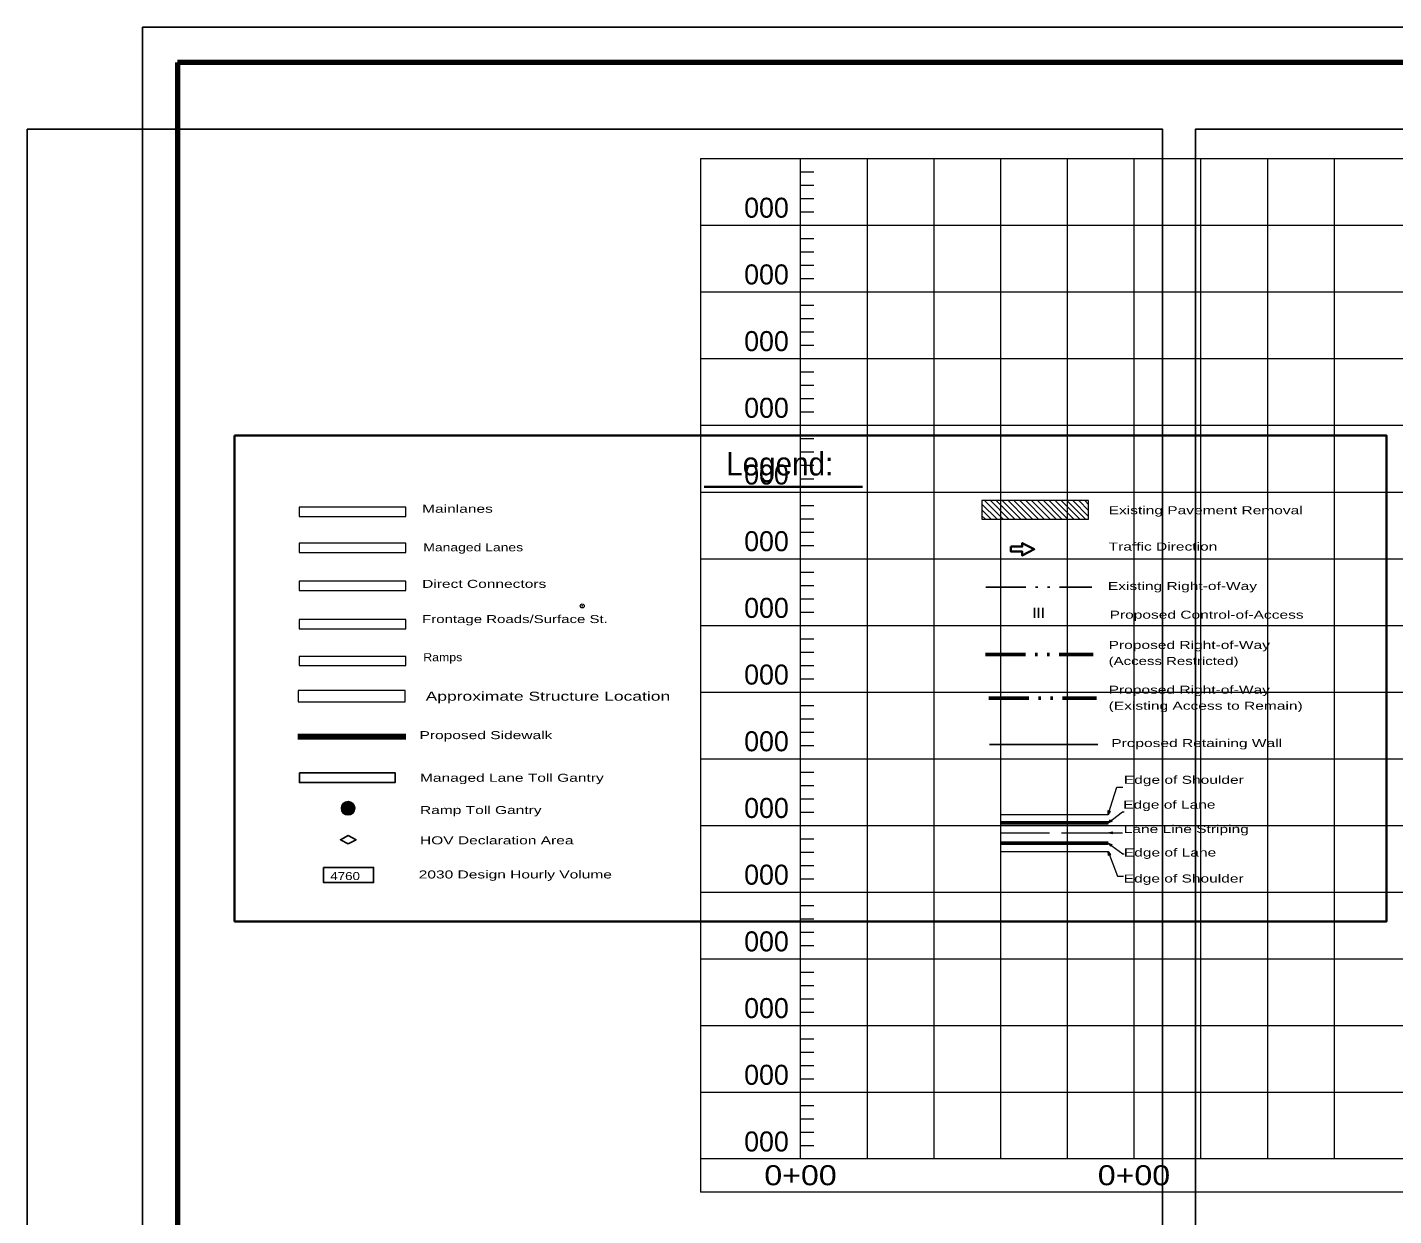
# Model space of a CAD drawing. Extents: x 2246932 to 2264252, y 7095151 to 7098651.
# Drawn here: x 2246932 to 2248981, y 7096869 to 7098651 of the extents above; entities that cross this region are included whole.
import ezdxf
from ezdxf.enums import TextEntityAlignment as Align

# ---------------------------------------------------------------- set-up
doc = ezdxf.new("R2010")
doc.units = 0
doc.header["$LTSCALE"] = 12
doc.header["$PDMODE"] = 32
doc.header["$PDSIZE"] = 6
doc.linetypes.add('DASH_DOUBLE_DOT', pattern=[9.2, 5, -1.2, 0.3, -1.2, 0.3, -1.2])
doc.linetypes.add('LONG_DASHED', pattern=[7.5, 6, -1.5])
for name, color, linetype, lineweight in [('1', 7, 'Continuous', 80), ('21', 7, 'Continuous', 13), ('62', 7, 'Continuous', 13), ('63', 7, 'Continuous', 25)]:
    doc.layers.add(name, color=color, linetype=linetype, lineweight=lineweight)
doc.layers.add('22', color=7, linetype='Continuous')

msp = doc.modelspace()

# ---------------------------------------------------------------- hatches: boundary and pattern name
at = {"layer": '21'}
for points in [[(2247422.99, 7097479.89, 1), (2247403.01, 7097479.89, 1)], [(2248555.86, 7097475.64), (2248552.59, 7097470.39), (2248553.01, 7097476.56)], [(2248558.25, 7097460.37), (2248552.59, 7097457.89), (2248556.42, 7097462.74)], [(2248558.62, 7097441.5), (2248552.59, 7097442.89), (2248558.56, 7097444.5)], [(2248556.52, 7097423.12), (2248552.59, 7097427.89), (2248558.31, 7097425.53)], [(2248553.33, 7097409.25), (2248552.59, 7097415.39), (2248556.14, 7097410.32)]]:
    msp.add_hatch(color=256, dxfattribs=at).paths.add_polyline_path(points)

# ---------------------------------------------------------------- linework, layer by layer
at = {"layer": '1'}
for p, q in [((2247157.08, 7098598.35), (2247157.09, 7095203.35)), ((2264052.09, 7098598.35), (2247157.09, 7098598.35))]:
    msp.add_line(p, q, dxfattribs=at)
at = {"layer": '1', "lineweight": 25}
msp.add_lwpolyline([(2264104.59, 7095150.85), (2264104.59, 7098650.85), (2247104.59, 7098650.85), (2247104.59, 7095150.85)], dxfattribs=at)
at = {"layer": '21', "lineweight": 35}
msp.add_line((2247947.17, 7097961.8), (2248184.63, 7097961.8), dxfattribs=at)
at = {"layer": '21'}
for p, q in [((2248386.29, 7097913.34), (2248363.52, 7097936.11)), ((2248395.13, 7097913.34), (2248367.3, 7097941.18)), ((2248403.97, 7097913.34), (2248376.14, 7097941.18)), ((2248412.81, 7097913.34), (2248384.98, 7097941.18)), ((2248421.65, 7097913.34), (2248393.81, 7097941.18)), ((2248430.49, 7097913.34), (2248402.65, 7097941.18)), ((2248439.33, 7097913.34), (2248411.49, 7097941.18)), ((2248448.17, 7097913.34), (2248420.33, 7097941.18)), ((2248457.01, 7097913.34), (2248429.17, 7097941.18)), ((2248465.84, 7097913.34), (2248438.01, 7097941.18)), ((2248474.68, 7097913.34), (2248446.85, 7097941.18)), ((2248483.52, 7097913.34), (2248455.69, 7097941.18)), ((2248492.36, 7097913.34), (2248464.52, 7097941.18)), ((2248501.2, 7097913.34), (2248473.36, 7097941.18)), ((2248510.04, 7097913.34), (2248482.2, 7097941.18)), ((2248518.88, 7097913.34), (2248491.04, 7097941.18)), ((2248523.53, 7097917.53), (2248499.88, 7097941.18)), ((2248523.53, 7097926.36), (2248508.72, 7097941.18)), ((2248523.53, 7097935.2), (2248517.56, 7097941.18)), ((2248377.46, 7097913.34), (2248363.52, 7097927.27)), ((2248368.62, 7097913.34), (2248363.52, 7097918.43)), ((2248552.59, 7097470.39), (2248565.97, 7097511.8)), ((2248565.97, 7097511.8), (2248574.73, 7097511.8)), ((2248392.58, 7097470.39), (2248552.59, 7097470.39)), ((2248552.59, 7097457.89), (2248574.48, 7097474.79)), ((2248574.48, 7097474.79), (2248576.75, 7097474.79)), ((2248552.59, 7097442.89), (2248574.48, 7097443.31)), ((2248552.59, 7097427.89), (2248574.91, 7097411.41)), ((2248392.58, 7097415.39), (2248552.59, 7097415.39)), ((2248552.59, 7097415.39), (2248566.82, 7097378.23)), ((2248574.91, 7097411.41), (2248577, 7097411.41)), ((2248566.82, 7097378.23), (2248575.74, 7097378.23))]:
    msp.add_line(p, q, dxfattribs=at)
at = {"layer": '21', "linetype": 'DASH_DOUBLE_DOT', "lineweight": 25}
msp.add_line((2248369.4, 7097811.29), (2248528.43, 7097811.29), dxfattribs=at)
at = {"layer": '21', "lineweight": 25}
for p, q in [((2248442.16, 7097780.54), (2248442.16, 7097765.54)), ((2248448.41, 7097780.54), (2248448.41, 7097765.54)), ((2248454.66, 7097780.54), (2248454.66, 7097765.54)), ((2248375.07, 7097575.48), (2248537.1, 7097575.48))]:
    msp.add_line(p, q, dxfattribs=at)
at = {"layer": '21', "linetype": 'DASH_DOUBLE_DOT', "lineweight": 53}
for p, q in [((2248368.86, 7097710.68), (2248530.41, 7097710.68)), ((2248373.74, 7097645.27), (2248535.3, 7097645.27))]:
    msp.add_line(p, q, dxfattribs=at)
at = {"layer": '21', "lineweight": 106}
msp.add_line((2247337.89, 7097587.33), (2247499.92, 7097587.33), dxfattribs=at)
at = {"layer": '21', "lineweight": 53}
for p, q in [((2248392.58, 7097457.89), (2248552.59, 7097457.89)), ((2248392.58, 7097427.89), (2248552.59, 7097427.89))]:
    msp.add_line(p, q, dxfattribs=at)
at = {"layer": '21', "linetype": 'LONG_DASHED'}
msp.add_line((2248392.58, 7097442.89), (2248552.59, 7097442.89), dxfattribs=at)
at = {"layer": '21', "lineweight": 35}
for points in [[(2247242.96, 7098038.69), (2248970.28, 7098038.69), (2248970.28, 7097310.27), (2247242.96, 7097310.27)], [(2248407.04, 7097872.4), (2248407.03, 7097864.89), (2248424.05, 7097864.87), (2248424.04, 7097858.78), (2248442.06, 7097868.21), (2248424.06, 7097877.67), (2248424.06, 7097872.38)]]:
    msp.add_lwpolyline(points, close=True, dxfattribs=at)
at = {"layer": '21'}
for points in [[(2247339.66, 7097917.61), (2247499.71, 7097917.61), (2247499.71, 7097931.45), (2247339.66, 7097931.45)], [(2248363.52, 7097913.34), (2248523.53, 7097913.34), (2248523.53, 7097941.18), (2248363.52, 7097941.18)], [(2247339.66, 7097863.38), (2247499.71, 7097863.38), (2247499.71, 7097877.22), (2247339.66, 7097877.22)], [(2247339.66, 7097806.7), (2247499.71, 7097806.7), (2247499.71, 7097820.54), (2247339.66, 7097820.54)], [(2247339.66, 7097749.07), (2247499.71, 7097749.07), (2247499.71, 7097762.91), (2247339.66, 7097762.91)], [(2247339.66, 7097693.79), (2247499.71, 7097693.79), (2247499.71, 7097707.62), (2247339.66, 7097707.62)], [(2247338.12, 7097639.59), (2247498.52, 7097639.57), (2247498.52, 7097656.53), (2247338.12, 7097656.56)], [(2248555.86, 7097475.64), (2248552.59, 7097470.39), (2248553.01, 7097476.56)], [(2248558.25, 7097460.37), (2248552.59, 7097457.89), (2248556.42, 7097462.74)], [(2248558.62, 7097441.5), (2248552.59, 7097442.89), (2248558.56, 7097444.5)], [(2248556.52, 7097423.12), (2248552.59, 7097427.89), (2248558.31, 7097425.53)], [(2248553.33, 7097409.25), (2248552.59, 7097415.39), (2248556.14, 7097410.32)]]:
    msp.add_lwpolyline(points, close=True, dxfattribs=at)
at = {"layer": '21', "lineweight": 25}
for points in [[(2247340.2, 7097533.25), (2247483.52, 7097533.25), (2247483.52, 7097518.52), (2247340.2, 7097518.52)], [(2247413.4, 7097426.51), (2247425.11, 7097432.82), (2247413.4, 7097439.13), (2247401.68, 7097432.82)], [(2247376.38, 7097391.28), (2247451.24, 7097391.28), (2247451.24, 7097368.62), (2247376.38, 7097368.62)]]:
    msp.add_lwpolyline(points, close=True, dxfattribs=at)
msp.add_circle((2247413, 7097479.89), 9.99, dxfattribs=at)
at = {"layer": '21'}
msp.add_point((2247764.18, 7097783.24), dxfattribs=at)
at = {"layer": '62'}
for p, q in [((2247941.45, 7098454.14), (2247941.45, 7096904.14)), ((2247941.45, 7098454.14), (2263241.45, 7098454.14)), ((2248091.45, 7096954.14), (2248091.45, 7098454.14)), ((2248191.45, 7098454.14), (2248191.45, 7096954.14)), ((2248291.45, 7098454.14), (2248291.45, 7096954.14)), ((2248391.45, 7098454.14), (2248391.45, 7096954.14)), ((2248491.45, 7098454.14), (2248491.45, 7096954.14)), ((2248591.45, 7098454.14), (2248591.45, 7096954.14)), ((2248691.45, 7098454.14), (2248691.45, 7096954.14)), ((2248791.45, 7098454.14), (2248791.45, 7096954.14)), ((2248891.45, 7098454.14), (2248891.45, 7096954.14)), ((2248091.45, 7098434.14), (2248111.45, 7098434.14)), ((2248091.45, 7098414.14), (2248111.45, 7098414.14)), ((2248091.45, 7098394.14), (2248111.45, 7098394.14)), ((2248091.45, 7098374.14), (2248111.45, 7098374.14)), ((2247941.45, 7098354.14), (2248091.45, 7098354.14)), ((2248091.45, 7098334.14), (2248111.45, 7098334.14)), ((2248091.45, 7098314.14), (2248111.45, 7098314.14)), ((2248091.45, 7098294.14), (2248111.45, 7098294.14)), ((2248091.45, 7098274.14), (2248111.45, 7098274.14)), ((2247941.45, 7098254.14), (2248091.45, 7098254.14)), ((2248091.45, 7098234.14), (2248111.45, 7098234.14)), ((2248091.45, 7098214.14), (2248111.45, 7098214.14)), ((2248091.45, 7098194.14), (2248111.45, 7098194.14)), ((2248091.45, 7098174.14), (2248111.45, 7098174.14)), ((2247941.45, 7098154.14), (2248091.45, 7098154.14)), ((2248091.45, 7098134.14), (2248111.45, 7098134.14)), ((2248091.45, 7098114.14), (2248111.45, 7098114.14)), ((2248091.45, 7098094.14), (2248111.45, 7098094.14)), ((2248091.45, 7098074.14), (2248111.45, 7098074.14)), ((2247941.45, 7098054.14), (2248091.45, 7098054.14)), ((2248091.45, 7098034.14), (2248111.45, 7098034.14)), ((2248091.45, 7098014.14), (2248111.45, 7098014.14)), ((2248091.45, 7097994.14), (2248111.45, 7097994.14)), ((2248091.45, 7097974.14), (2248111.45, 7097974.14)), ((2247941.45, 7097954.14), (2248091.45, 7097954.14)), ((2248091.45, 7097934.14), (2248111.45, 7097934.14)), ((2248091.45, 7097914.14), (2248111.45, 7097914.14)), ((2248091.45, 7097894.14), (2248111.45, 7097894.14)), ((2248091.45, 7097874.14), (2248111.45, 7097874.14)), ((2247941.45, 7097854.14), (2248091.45, 7097854.14)), ((2248091.45, 7097834.14), (2248111.45, 7097834.14)), ((2248091.45, 7097814.14), (2248111.45, 7097814.14)), ((2248091.45, 7097794.14), (2248111.45, 7097794.14)), ((2248091.45, 7097774.14), (2248111.45, 7097774.14)), ((2247941.45, 7097754.14), (2248091.45, 7097754.14)), ((2248091.45, 7097734.14), (2248111.45, 7097734.14)), ((2248091.45, 7097714.14), (2248111.45, 7097714.14)), ((2248091.45, 7097694.14), (2248111.45, 7097694.14)), ((2248091.45, 7097674.14), (2248111.45, 7097674.14)), ((2247941.45, 7097654.14), (2248091.45, 7097654.14)), ((2248091.45, 7097634.14), (2248111.45, 7097634.14)), ((2248091.45, 7097614.14), (2248111.45, 7097614.14)), ((2248091.45, 7097594.14), (2248111.45, 7097594.14)), ((2248091.45, 7097574.14), (2248111.45, 7097574.14)), ((2247941.45, 7097554.14), (2248091.45, 7097554.14)), ((2248091.45, 7097534.14), (2248111.45, 7097534.14)), ((2248091.45, 7097514.14), (2248111.45, 7097514.14)), ((2248091.45, 7097494.14), (2248111.45, 7097494.14)), ((2248091.45, 7097474.14), (2248111.45, 7097474.14)), ((2247941.45, 7097454.14), (2248091.45, 7097454.14)), ((2248091.45, 7097434.14), (2248111.45, 7097434.14)), ((2248091.45, 7097414.14), (2248111.45, 7097414.14)), ((2248091.45, 7097394.14), (2248111.45, 7097394.14)), ((2248091.45, 7097374.14), (2248111.45, 7097374.14)), ((2247941.45, 7097354.14), (2248091.45, 7097354.14)), ((2248091.45, 7097334.14), (2248111.45, 7097334.14)), ((2248091.45, 7097314.14), (2248111.45, 7097314.14)), ((2248091.45, 7097294.14), (2248111.45, 7097294.14)), ((2248091.45, 7097274.14), (2248111.45, 7097274.14)), ((2247941.45, 7097254.14), (2248091.45, 7097254.14)), ((2248091.45, 7097234.14), (2248111.45, 7097234.14)), ((2248091.45, 7097214.14), (2248111.45, 7097214.14)), ((2248091.45, 7097194.14), (2248111.45, 7097194.14)), ((2248091.45, 7097174.14), (2248111.45, 7097174.14)), ((2247941.45, 7097154.14), (2248091.45, 7097154.14)), ((2248091.45, 7097134.14), (2248111.45, 7097134.14)), ((2248091.45, 7097114.14), (2248111.45, 7097114.14)), ((2248091.45, 7097094.14), (2248111.45, 7097094.14)), ((2248091.45, 7097074.14), (2248111.45, 7097074.14)), ((2247941.45, 7097054.14), (2248091.45, 7097054.14)), ((2248091.45, 7097034.14), (2248111.45, 7097034.14)), ((2248091.45, 7097014.14), (2248111.45, 7097014.14)), ((2248091.45, 7096994.14), (2248111.45, 7096994.14)), ((2248091.45, 7096974.14), (2248111.45, 7096974.14)), ((2263241.45, 7096954.14), (2247941.45, 7096954.14)), ((2263241.45, 7096904.14), (2247941.45, 7096904.14))]:
    msp.add_line(p, q, dxfattribs=at)
for points in [[(2248091.45, 7098354.14), (2263091.45, 7098354.14), (2263241.45, 7098354.14)], [(2248091.45, 7098254.14), (2263091.45, 7098254.14), (2263241.45, 7098254.14)], [(2248091.45, 7098154.14), (2263091.45, 7098154.14), (2263241.45, 7098154.14)], [(2248091.45, 7098054.14), (2263091.45, 7098054.14), (2263241.45, 7098054.14)], [(2248091.45, 7097954.14), (2263091.45, 7097954.14), (2263241.45, 7097954.14)], [(2248091.45, 7097854.14), (2263091.45, 7097854.14), (2263241.45, 7097854.14)], [(2248091.45, 7097754.14), (2263091.45, 7097754.14), (2263241.45, 7097754.14)], [(2248091.45, 7097654.14), (2263091.45, 7097654.14), (2263241.45, 7097654.14)], [(2248091.45, 7097554.14), (2263091.45, 7097554.14), (2263241.45, 7097554.14)], [(2248091.45, 7097454.14), (2263091.45, 7097454.14), (2263241.45, 7097454.14)], [(2248091.45, 7097354.14), (2263091.45, 7097354.14), (2263241.45, 7097354.14)], [(2248091.45, 7097254.14), (2263091.45, 7097254.14), (2263241.45, 7097254.14)], [(2248091.45, 7097154.14), (2263091.45, 7097154.14), (2263241.45, 7097154.14)], [(2248091.45, 7097054.14), (2263091.45, 7097054.14), (2263241.45, 7097054.14)]]:
    msp.add_lwpolyline(points, dxfattribs=at)
at = {"layer": '63'}
for points in [[(2248634.3, 7095298.54), (2246932.14, 7095298.54), (2246932.14, 7098498.04), (2248634.3, 7098498.04)], [(2250385.73, 7095298.54), (2248683.57, 7095298.54), (2248683.57, 7098498.04), (2250385.73, 7098498.04)]]:
    msp.add_lwpolyline(points, close=True, dxfattribs=at)

# ---------------------------------------------------------------- texts
at = {"layer": '21'}
for s, height, width, p in [('Legend:', 35, 0.95, (2247979.89, 7097978.95)), ('Mainlanes', 12, 1.45, (2247524.09, 7097923.05)), ('Existing Pavement Removal', 12, 1.45, (2248553.49, 7097920.8)), ('Managed Lanes', 12, 1.3, (2247525.89, 7097865.25)), ('Traffic Direction', 12, 1.45, (2248553.49, 7097866.33)), ('Direct Connectors', 12, 1.45, (2247524.09, 7097810.45)), ('Existing Right-of-Way', 12, 1.45, (2248552.29, 7097807.21)), ('Frontage Roads/Surface St.', 12, 1.4, (2247524.09, 7097757.65)), ('Proposed Control-of-Access', 12, 1.45, (2248554.89, 7097764.21)), ('Proposed Right-of-Way', 12, 1.45, (2248553.49, 7097718.82)), ('Ramps', 12, 1.15, (2247525.89, 7097700.45)), ('(Access Restricted)', 12, 1.4, (2248553.49, 7097694.82)), ('Approximate Structure Location', 13.5, 1.45, (2247529.39, 7097641.23)), ('Proposed Right-of-Way ', 12, 1.45, (2248553.49, 7097651.71)), ('(Existing Access to Remain)', 12, 1.45, (2248553.49, 7097627.71)), ('Proposed Sidewalk', 12, 1.45, (2247520.21, 7097583.63)), ('Proposed Retaining Wall', 12, 1.45, (2248557.39, 7097571.75)), ('Managed Lane Toll Gantry', 12, 1.45, (2247520.9, 7097519.71)), ('Edge of Shoulder', 12, 1.45, (2248576.32, 7097516.65)), ('Ramp Toll Gantry', 12, 1.45, (2247520.9, 7097471.31)), ('Edge of Lane', 12, 1.45, (2248575.32, 7097479.45)), ('Lane Line Striping', 12, 1.45, (2248576.12, 7097442.85)), ('HOV Declaration Area', 12, 1.45, (2247520.9, 7097425.91)), ('Edge of Lane', 12, 1.45, (2248576.32, 7097407.65)), ('2030 Design Hourly Volume', 12, 1.45, (2247519, 7097374.73)), ('Edge of Shoulder', 12, 1.45, (2248576.12, 7097368.65))]:
    msp.add_text(s, height=height, dxfattribs=dict(at, width=width)).set_placement(p)
at = {"layer": '21', "width": 1.25}
msp.add_text('4760', height=12, dxfattribs=at).set_placement((2247408.64, 7097372.33), align=Align.CENTER)
at = {"layer": '22'}
for p in [(2248006.99, 7098365.4), (2248006.99, 7098265.4), (2248006.99, 7098165.4), (2248006.99, 7098065.4), (2248006.99, 7097965.4), (2248006.99, 7097865.4), (2248006.99, 7097765.4), (2248006.99, 7097665.4), (2248006.99, 7097565.4), (2248006.99, 7097465.4), (2248006.99, 7097365.4), (2248006.99, 7097265.4), (2248006.99, 7097165.4), (2248006.99, 7097065.4), (2248006.99, 7096965.4)]:
    msp.add_text('000', height=30, dxfattribs=at).set_placement(p)
at = {"layer": '22', "width": 1.2}
for p in [(2248091.45, 7096914.74), (2248591.45, 7096914.74)]:
    msp.add_text('0+00', height=30, dxfattribs=at).set_placement(p, align=Align.CENTER)

doc.saveas('drawing.dxf')
